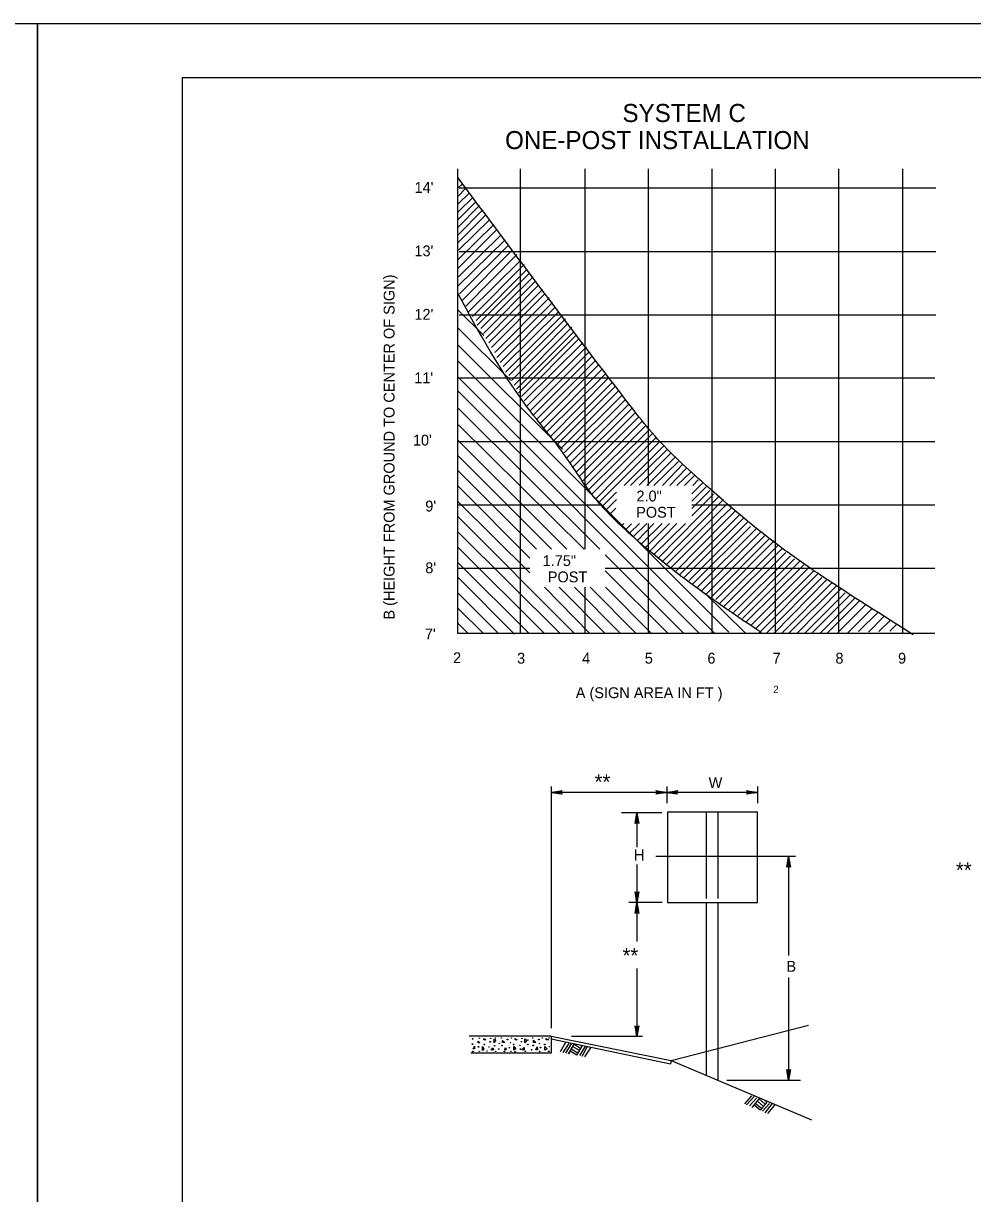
# Model space of a CAD drawing. Extents: x 644358 to 648627, y 294594 to 295782.
# Drawn here: x 646877.4 to 647140.2, y 295457.6 to 295781.6 of the extents above; entities that cross this region are included whole.
import ezdxf

# ---------------------------------------------------------------- set-up
doc = ezdxf.new("R2010")
doc.units = 0
for name, color, linetype in [('1', 7, 'Continuous'), ('10', 7, 'Continuous'), ('2', 7, 'Continuous'), ('3', 7, 'Continuous'), ('4', 7, 'Continuous'), ('PLT-BNDY', 7, 'Continuous')]:
    doc.layers.add(name, color=color, linetype=linetype)

# ---------------------------------------------------------------- blocks, each defined once
blk = doc.blocks.new('RARROW')
at = {"layer": '3'}
blk.add_lwpolyline([(-2.2695, 0.285), (-2.184875, 0.12075), (0, 0), (-2.2695, 0.285), (-2.38575, 0.384625), (0, 0), (-2.183125, -0.108), (-2.262875, -0.2705), (0, 0), (-2.38575, -0.379125), (-2.262875, -0.2705)], dxfattribs=at)

msp = doc.modelspace()

# ---------------------------------------------------------------- linework, layer by layer
at = {"layer": '1'}
for p, q in [((646921.31, 295766.63), (647707.31, 295766.63)), ((646921.31, 295766.63), (646921.31, 295202.63)), ((647027.52, 295499.45), (647026.02, 295496.82)), ((647028.4, 295499.2), (647026.77, 295496.7)), ((647029.02, 295499.07), (647027.52, 295496.45)), ((647029.77, 295498.95), (647028.27, 295496.32)), ((647030.65, 295495.95), (647028.77, 295497.07)), ((647030.9, 295496.45), (647029.02, 295497.57)), ((647031.4, 295497.2), (647029.4, 295498.32)), ((647031.77, 295497.7), (647029.77, 295498.95)), ((647032.02, 295498.45), (647030.52, 295495.95)), ((647032.9, 295498.32), (647031.4, 295495.82)), ((647032.02, 295498.32), (647031.77, 295498.57)), ((647033.52, 295498.2), (647032.02, 295495.57)), ((647034.4, 295497.95), (647032.77, 295495.45)), ((647028.65, 295496.32), (647028.27, 295496.45)), ((647079.02, 295484.7), (647077.02, 295482.45)), ((647079.77, 295484.45), (647077.65, 295482.2)), ((647080.4, 295484.07), (647078.4, 295481.95)), ((647081.15, 295483.95), (647079.15, 295481.57)), ((647082.77, 295482.32), (647081.15, 295483.82)), ((647079.4, 295481.45), (647079.15, 295481.7)), ((647081.4, 295480.7), (647079.65, 295482.2)), ((647081.77, 295481.2), (647080.02, 295482.57)), ((647082.27, 295481.7), (647080.52, 295483.32)), ((647083.27, 295482.95), (647081.4, 295480.7)), ((647084.02, 295482.57), (647082.02, 295480.45)), ((647084.65, 295482.45), (647082.65, 295479.95)), ((647083.15, 295482.82), (647082.9, 295483.07)), ((647085.4, 295482.07), (647083.4, 295479.82))]:
    msp.add_line(p, q, dxfattribs=at)
for points in [[(647004.9, 295500.2), (647004.9, 295500.57), (647005.4, 295500.2)], [(647007.77, 295499.32), (647007.77, 295500.45), (647008.15, 295499.95)], [(647013.52, 295500.2), (647013.52, 295500.57), (647014.15, 295500.2)], [(647016.27, 295499.32), (647016.27, 295500.45), (647016.9, 295499.95)], [(647018.65, 295499.45), (647018.65, 295500.07), (647019.27, 295499.45)], [(647022.15, 295500.2), (647022.15, 295500.57), (647022.77, 295500.2)], [(647002.27, 295498.45), (647002.27, 295497.7), (647001.9, 295497.7)], [(647003.27, 295499.32), (647003.27, 295499.82), (647003.77, 295499.32)], [(647004.52, 295497.2), (647004.52, 295498.32), (647004.9, 295497.7)], [(647007.4, 295497.95), (647007.52, 295497.45), (647006.9, 295497.32)], [(647010.02, 295499.45), (647010.02, 295499.95), (647010.65, 295499.45)], [(647010.9, 295498.07), (647011.02, 295497.45), (647010.65, 295497.45)], [(647013.15, 295497.32), (647013.15, 295498.32), (647013.77, 295497.7)], [(647016.02, 295498.07), (647016.02, 295497.45), (647015.52, 295497.32)], [(647019.65, 295498.2), (647019.77, 295497.45), (647019.27, 295497.45)], [(647021.77, 295497.32), (647021.77, 295498.32), (647022.4, 295497.7)]]:
    msp.add_lwpolyline(points, close=True, dxfattribs=at)
for centre, radius in [((647001.78, 295500.46), 0.0979), ((647003.72, 295500.64), 0.056), ((647006.79, 295500.58), 0.056), ((647008.11, 295500.67), 0.056), ((647009.73, 295500.7), 0.056), ((647011.41, 295500.27), 0.0979), ((647012.46, 295500.67), 0.056), ((647015.41, 295500.6), 0.056), ((647017.13, 295500.14), 0.056), ((647018.36, 295500.72), 0.056), ((647020.1, 295500.26), 0.0979), ((647021.09, 295500.69), 0.056), ((647022.93, 295500.66), 0.056), ((647001.72, 295498.96), 0.0979), ((647001.81, 295496.96), 0.0979), ((647003.41, 295498.26), 0.0979), ((647003.63, 295496.99), 0.056), ((647005.03, 295498.9), 0.0979), ((647005.74, 295497.11), 0.056), ((647006.27, 295498.22), 0.056), ((647006.63, 295499.62), 0.0979), ((647007.86, 295498.55), 0.0979), ((647008.16, 295496.99), 0.056), ((647009, 295497.63), 0.0979), ((647009.15, 295499.18), 0.056), ((647009.92, 295498.58), 0.0979), ((647010.56, 295496.99), 0.0979), ((647011.94, 295498), 0.0979), ((647012.26, 295499.4), 0.056), ((647012.37, 295497.02), 0.056), ((647013.14, 295498.89), 0.0979), ((647013.54, 295496.89), 0.0979), ((647014.89, 295498.64), 0.056), ((647015.04, 295497.59), 0.0979), ((647015.26, 295499.65), 0.0979), ((647016.36, 295497.01), 0.0979), ((647017.05, 295498.86), 0.0979), ((647018.11, 295497.41), 0.0979), ((647018.54, 295498.6), 0.0979), ((647020.32, 295496.97), 0.0979), ((647020.32, 295499.17), 0.056), ((647020.57, 295498.02), 0.0979), ((647021.76, 295498.91), 0.0979), ((647022.87, 295496.99), 0.0979), ((647022.97, 295498.27), 0.056)]:
    msp.add_circle(centre, radius, dxfattribs=at)
at = {"layer": '10'}
for p, q in [((646997.64, 295735.97), (646998.89, 295737.1)), ((646997.64, 295733.72), (646999.89, 295735.97)), ((646997.64, 295731.6), (647000.89, 295734.72)), ((646997.76, 295729.47), (647001.89, 295733.47)), ((646997.51, 295724.97), (647003.64, 295731.22)), ((646997.76, 295727.35), (647002.76, 295732.35)), ((646997.76, 295723.1), (647004.64, 295729.97)), ((646997.76, 295720.97), (647005.51, 295728.72)), ((646997.89, 295718.85), (647006.51, 295727.35)), ((646997.76, 295716.22), (647007.64, 295725.97)), ((646997.76, 295713.85), (647008.51, 295724.6)), ((646997.64, 295708.85), (647010.76, 295721.72)), ((646997.89, 295711.47), (647009.64, 295723.1)), ((646998.14, 295706.72), (647011.76, 295720.35)), ((646999.01, 295704.97), (647012.76, 295718.85)), ((646999.89, 295703.35), (647014.01, 295717.6)), ((647000.64, 295701.72), (647015.01, 295715.97)), ((647001.76, 295700.47), (647016.01, 295714.85)), ((647002.76, 295699.35), (647016.89, 295713.6)), ((647003.01, 295698.1), (647017.64, 295712.6)), ((647004.01, 295697.1), (647018.51, 295711.47)), ((647004.76, 295695.72), (647019.26, 295710.35)), ((647005.39, 295694.35), (647020.14, 295709.22)), ((647006.26, 295693.22), (647021.14, 295707.97)), ((647007.01, 295691.85), (647021.89, 295706.85)), ((647007.89, 295690.47), (647023.01, 295705.6)), ((647008.51, 295689.1), (647023.89, 295704.35)), ((647004.89, 295695.22), (646997.76, 295702.22)), ((647009.39, 295687.72), (647024.76, 295703.1)), ((647010.26, 295686.6), (647025.64, 295701.85)), ((647010.89, 295685.1), (647026.64, 295700.85)), ((647011.76, 295684.1), (647027.51, 295699.85)), ((647012.51, 295682.72), (647028.26, 295698.6)), ((647012.26, 295682.85), (646997.64, 295697.35)), ((647013.26, 295681.47), (647029.26, 295697.47)), ((647013.89, 295680.35), (647029.76, 295696.22)), ((647014.51, 295679.35), (647030.51, 295695.35)), ((647026.64, 295663.72), (646997.64, 295692.6)), ((647015.26, 295678.35), (647031.26, 295694.35)), ((647016.01, 295677.1), (647032.26, 295693.22)), ((647016.89, 295675.72), (647033.26, 295692.1)), ((647026.01, 295659.85), (646997.76, 295688.1)), ((647017.76, 295674.47), (647034.01, 295690.72)), ((647018.76, 295673.35), (647035.01, 295689.6)), ((647019.64, 295672.1), (647035.89, 295688.35)), ((647020.51, 295670.85), (647036.76, 295687.22)), ((647021.26, 295669.47), (647037.76, 295685.97)), ((647022.26, 295668.47), (647038.64, 295684.72)), ((647068.83, 295612.72), (646997.64, 295683.72)), ((647072.76, 295613.1), (647004.01, 295681.85)), ((647023.39, 295667.35), (647039.51, 295683.6)), ((647024.26, 295666.1), (647040.39, 295682.22)), ((647064.57, 295612.72), (646997.64, 295679.85)), ((647025.39, 295665.22), (647041.26, 295681.1)), ((647026.26, 295663.97), (647042.26, 295679.97)), ((647027.14, 295662.72), (647043.14, 295678.72)), ((647036.98, 295636.01), (646997.89, 295674.97)), ((647027.89, 295661.35), (647044.14, 295677.47)), ((647028.76, 295659.97), (647045.01, 295676.22)), ((647029.51, 295658.72), (647045.89, 295674.97)), ((647030.51, 295657.47), (647046.89, 295673.85)), ((647031.14, 295656.1), (647047.76, 295672.72)), ((647032.63, 295636.01), (646997.89, 295670.47)), ((647032.26, 295654.97), (647048.76, 295671.47)), ((647033.14, 295653.72), (647049.64, 295670.22)), ((647033.76, 295652.35), (647050.64, 295669.1)), ((647027.85, 295636.01), (646997.64, 295666.22)), ((647034.7, 295651.16), (647051.51, 295667.97)), ((647035.95, 295650.11), (647052.51, 295666.85)), ((647036.93, 295649.14), (647053.51, 295665.72)), ((647043.73, 295653.69), (647054.64, 295664.6)), ((647045.47, 295653.69), (647055.64, 295663.6)), ((647047.89, 295653.72), (647056.64, 295662.6)), ((647023.6, 295636.01), (646997.64, 295661.97)), ((647049.98, 295653.69), (647057.76, 295661.47)), ((647051.95, 295653.69), (647058.76, 295660.35)), ((647054.38, 295653.69), (647060.01, 295659.6)), ((647019.48, 295636.01), (646997.64, 295657.85)), ((647056.38, 295653.69), (647060.89, 295658.35)), ((647058.31, 295653.69), (647062.26, 295657.47)), ((647060.48, 295653.69), (647063.39, 295656.6)), ((647017.65, 295633.58), (646997.64, 295653.6)), ((647062.46, 295651.41), (647065.39, 295654.35)), ((647062.46, 295649.37), (647066.41, 295653.32)), ((647062.46, 295647.31), (647067.44, 295652.29)), ((647062.73, 295653.69), (647064.26, 295655.22)), ((647017.65, 295629.5), (646997.64, 295649.22)), ((647037.81, 295648.05), (647041.63, 295651.86)), ((647038.83, 295647.03), (647041.63, 295649.84)), ((647053.01, 295633.47), (647069.91, 295650.63)), ((647054.14, 295632.47), (647071.26, 295649.76)), ((647062.46, 295645.25), (647068.47, 295651.26)), ((647039.95, 295645.91), (647041.45, 295647.41)), ((647055.26, 295631.6), (647072.29, 295648.62)), ((647070.14, 295644.35), (647073.51, 295647.6)), ((647071.76, 295643.85), (647074.64, 295646.72)), ((647030.01, 295612.72), (646997.64, 295645.1)), ((647043.14, 295642.72), (647043.63, 295643.18)), ((647044.26, 295641.6), (647045.76, 295643.1)), ((647045.33, 295640.53), (647047.97, 295643.18)), ((647046.33, 295639.53), (647049.97, 295643.18)), ((647047.39, 295638.47), (647051.92, 295643.18)), ((647048.45, 295637.41), (647054.22, 295643.18)), ((647049.72, 295636.62), (647056.27, 295643.18)), ((647050.64, 295635.35), (647058.31, 295643.18)), ((647051.89, 295634.47), (647060.75, 295643.18)), ((647056.51, 295630.72), (647070.51, 295644.72)), ((647057.76, 295629.72), (647072.01, 295644.1)), ((647059.01, 295628.97), (647075.76, 295645.6)), ((647060.26, 295628.1), (647076.89, 295644.72)), ((647061.76, 295627.35), (647078.01, 295643.6)), ((647068.11, 295644.44), (647068.26, 295644.6)), ((647026.01, 295612.72), (646997.64, 295640.85)), ((647062.64, 295626.35), (647078.76, 295642.35)), ((647063.89, 295625.35), (647080.26, 295641.72)), ((647065.26, 295624.6), (647081.51, 295640.72)), ((647066.51, 295623.72), (647082.64, 295639.85)), ((647021.76, 295612.6), (646997.64, 295636.6)), ((647067.89, 295622.85), (647083.76, 295638.85)), ((647069.14, 295622.1), (647085.26, 295638.35)), ((647070.14, 295620.97), (647086.26, 295637.1)), ((647071.39, 295620.22), (647087.39, 295636.1)), ((647060.26, 295612.72), (647038.48, 295634.5)), ((647072.76, 295619.35), (647088.51, 295635.1)), ((647074.01, 295618.47), (647089.76, 295634.22)), ((647075.26, 295617.72), (647090.89, 295633.35)), ((647017.39, 295612.72), (646997.64, 295632.35)), ((647055.89, 295612.72), (647038.48, 295630.02)), ((647076.51, 295616.85), (647092.26, 295632.6)), ((647077.64, 295615.97), (647093.64, 295631.85)), ((647079.01, 295615.1), (647094.76, 295630.85)), ((647080.14, 295613.97), (647096.14, 295629.97)), ((647013.39, 295612.47), (646997.76, 295628.22)), ((647080.89, 295612.72), (647097.26, 295629.1)), ((647083.01, 295612.72), (647098.51, 295628.22)), ((647085.14, 295612.72), (647099.89, 295627.6)), ((647087.26, 295612.72), (647101.26, 295626.72)), ((647008.89, 295612.72), (646997.76, 295623.85)), ((647034.26, 295612.72), (647021.64, 295625.5)), ((647038.51, 295612.72), (647025.73, 295625.5)), ((647042.76, 295612.72), (647029.98, 295625.5)), ((647047.01, 295612.72), (647034.36, 295625.5)), ((647051.26, 295612.72), (647038.58, 295625.5)), ((647077.26, 295612.85), (647066.01, 295623.97)), ((647089.26, 295612.72), (647102.51, 295625.85)), ((647091.51, 295612.72), (647103.76, 295625.1)), ((647093.64, 295612.72), (647104.89, 295623.97)), ((647095.64, 295612.72), (647106.26, 295623.35)), ((647097.89, 295612.72), (647107.51, 295622.35)), ((647099.89, 295612.72), (647108.89, 295621.72)), ((647102.89, 295612.97), (647110.64, 295620.72)), ((647004.76, 295612.72), (646997.76, 295619.6)), ((647105.64, 295612.85), (647112.51, 295619.72)), ((647108.64, 295613.22), (647114.14, 295618.72)), ((647111.39, 295613.1), (647115.76, 295617.47)), ((647000.51, 295612.72), (646997.76, 295615.47)), ((647114.26, 295613.22), (647117.51, 295616.35)), ((647117.26, 295613.35), (647119.14, 295615.22))]:
    msp.add_line(p, q, dxfattribs=at)
at = {"layer": '2'}
for p, q in [((646997.64, 295612.72), (646997.64, 295741.35)), ((647015.01, 295630.72), (647015.01, 295741.35)), ((647032.89, 295636.01), (647032.89, 295741.35)), ((647050.51, 295653.69), (647050.51, 295741.35)), ((647068.14, 295648.22), (647068.14, 295741.35)), ((647085.64, 295638.35), (647085.64, 295741.35)), ((647103.14, 295612.72), (647103.14, 295741.35)), ((647120.76, 295741.35), (647120.76, 295612.72)), ((647130.01, 295735.97), (646998.01, 295735.97)), ((647130.01, 295718.35), (646998.01, 295718.35)), ((647130.01, 295700.85), (646998.01, 295700.85)), ((647129.76, 295683.35), (646997.76, 295683.35)), ((647129.76, 295665.72), (646997.76, 295665.72)), ((647037.64, 295648.22), (646997.76, 295648.22)), ((647129.76, 295648.22), (647062.46, 295648.22)), ((647068.14, 295612.72), (647068.14, 295648.22)), ((647050.51, 295612.72), (647050.51, 295643.18)), ((647085.64, 295612.72), (647085.64, 295638.72)), ((647017.65, 295630.72), (646997.64, 295630.72)), ((647015.01, 295612.72), (647015.01, 295630.72)), ((647129.76, 295630.72), (647038.48, 295630.72)), ((647032.89, 295612.72), (647032.89, 295625.5)), ((647129.76, 295612.72), (646997.64, 295612.72)), ((647055.77, 295563.2), (647055.77, 295538.2)), ((647080.65, 295563.2), (647055.77, 295563.2)), ((647066.4, 295563.2), (647066.4, 295539.32)), ((647069.65, 295563.2), (647069.65, 295539.32)), ((647080.65, 295538.2), (647080.65, 295563.2)), ((647055.77, 295538.2), (647080.65, 295538.2)), ((647066.4, 295538.07), (647066.4, 295490.2)), ((647069.65, 295538.2), (647069.65, 295488.95)), ((647056.77, 295494.45), (647094.77, 295504.2)), ((647023.52, 295501.2), (647000.77, 295501.2)), ((647023.52, 295501.2), (647023.52, 295496.45)), ((647023.52, 295501.2), (647056.77, 295494.45)), ((647023.52, 295500.45), (647056.52, 295493.57)), ((647023.52, 295496.45), (647001.27, 295496.45)), ((647056.77, 295494.45), (647056.52, 295493.57)), ((647056.77, 295494.45), (647095.65, 295478.07))]:
    msp.add_line(p, q, dxfattribs=at)
at = {"layer": '4'}
for p, q in [((647023.52, 295570.32), (647023.52, 295503.45)), ((647055.52, 295568.7), (647023.52, 295568.7)), ((647055.52, 295570.32), (647055.52, 295565.7)), ((647080.65, 295568.7), (647055.52, 295568.7)), ((647080.65, 295570.32), (647080.65, 295565.7)), ((647054.15, 295563.07), (647043.02, 295563.07)), ((647047.27, 295563.07), (647047.27, 295553.57)), ((647047.27, 295548.7), (647047.27, 295538.2)), ((647091.15, 295550.95), (647052.52, 295550.95)), ((647089.27, 295550.95), (647089.27, 295523.57)), ((647054.27, 295538.2), (647045.02, 295538.2)), ((647047.27, 295538.2), (647047.27, 295527.45)), ((647047.27, 295519.95), (647047.27, 295501.07)), ((647089.27, 295517.45), (647089.27, 295488.95)), ((647048.77, 295501.07), (647029.15, 295501.07)), ((647092.52, 295488.95), (647072.15, 295488.95))]:
    msp.add_line(p, q, dxfattribs=at)
for points in [[(647123.76, 295612.35), (647098.51, 295628.6), (647088.26, 295635.72), (647065.14, 295654.85), (647051.51, 295668.22), (647045.76, 295675.35), (646997.76, 295738.85)], [(647081.64, 295612.97), (647056.39, 295630.97), (647048.51, 295637.47), (647034.89, 295651.1), (647027.51, 295661.72), (647016.64, 295675.72), (646997.76, 295706.72)]]:
    msp.add_spline(points, degree=3, dxfattribs=at)
at = {"layer": 'PLT-BNDY'}
for points in [[(646040.31, 295781.63), (646881.31, 295781.63), (646881.31, 295187.63), (646040.31, 295187.63)], [(646881.31, 295781.63), (647722.31, 295781.63), (647722.31, 295187.63), (646881.31, 295187.63)]]:
    msp.add_lwpolyline(points, close=True, dxfattribs=at)

# ---------------------------------------------------------------- block references
at = {"layer": '2', "xscale": 1.2574347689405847, "yscale": 1.3092961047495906}
for p, rotation in [((647023.52, 295568.7), 180), ((647055.52, 295568.7), 180), ((647047.27, 295563.07), 89.99999999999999), ((647089.27, 295550.95), 89.99999999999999), ((647047.27, 295538.2), -90.00000000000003), ((647047.27, 295538.2), 89.99999999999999), ((647047.27, 295501.07), -90.00000000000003), ((647089.27, 295488.95), -90.00000000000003)]:
    msp.add_blockref('RARROW', p, dxfattribs=dict(at, rotation=rotation))
for p in [(647055.52, 295568.7), (647080.65, 295568.7)]:
    msp.add_blockref('RARROW', p, dxfattribs=at)

# ---------------------------------------------------------------- texts
at = {"layer": '4'}
for s, height, p in [('SYSTEM C', 5, (647043.26, 295754.32)), ('ONE-POST INSTALLATION', 5, (647010.76, 295746.82)), ("14'", 3, (646985.69, 295734.71)), ("13'", 3, (646985.66, 295717.13)), ("12'", 3, (646985.66, 295699.57)), ("11'", 3, (646985.6, 295681.97)), ("10'", 3, (646985.24, 295664.73)), ('2.0"', 3, (647047.14, 295649.26)), ("9'", 3, (646988.66, 295646.48)), ('POST', 3, (647047.06, 295644.76)), ('1.75"', 3, (647021.17, 295631.36)), ("8'", 3, (646988.66, 295629.36)), ('POST', 3, (647022.59, 295626.86)), ("7'", 3, (646988.55, 295611.06)), ('2', 3, (646996.35, 295604.48)), ('3', 3, (647014.09, 295604.35)), ('4', 3, (647032.1, 295604.35)), ('5', 3, (647049.45, 295604.35)), ('6', 3, (647066.78, 295604.35)), ('7', 3, (647084.82, 295604.35)), ('8', 3, (647102.23, 295604.35)), ('9', 3, (647119.57, 295604.35)), ('2', 2, (647085.02, 295596.23)), ('**', 4.2, (647035.55, 295569.51)), ('W', 3, (647067.12, 295569.9)), ('H', 3.09, (647046.4, 295549.82)), ('**', 4.2, (647135.59, 295545.1)), ('**', 4.2, (647043.28, 295521.42)), ('B', 3, (647088.66, 295519.04))]:
    msp.add_text(s, height=height, dxfattribs=at).set_placement(p)
for s, rotation, p in [(' B (HEIGHT FROM GROUND TO CENTER OF SIGN)', 90, (646980.15, 295615.43)), ('A (SIGN AREA IN FT )', 360, (647030.33, 295594.79))]:
    msp.add_text(s, height=3.005, rotation=rotation, dxfattribs=at).set_placement(p)

doc.saveas('drawing.dxf')
